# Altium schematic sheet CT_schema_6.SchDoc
size 582 x 363 mm
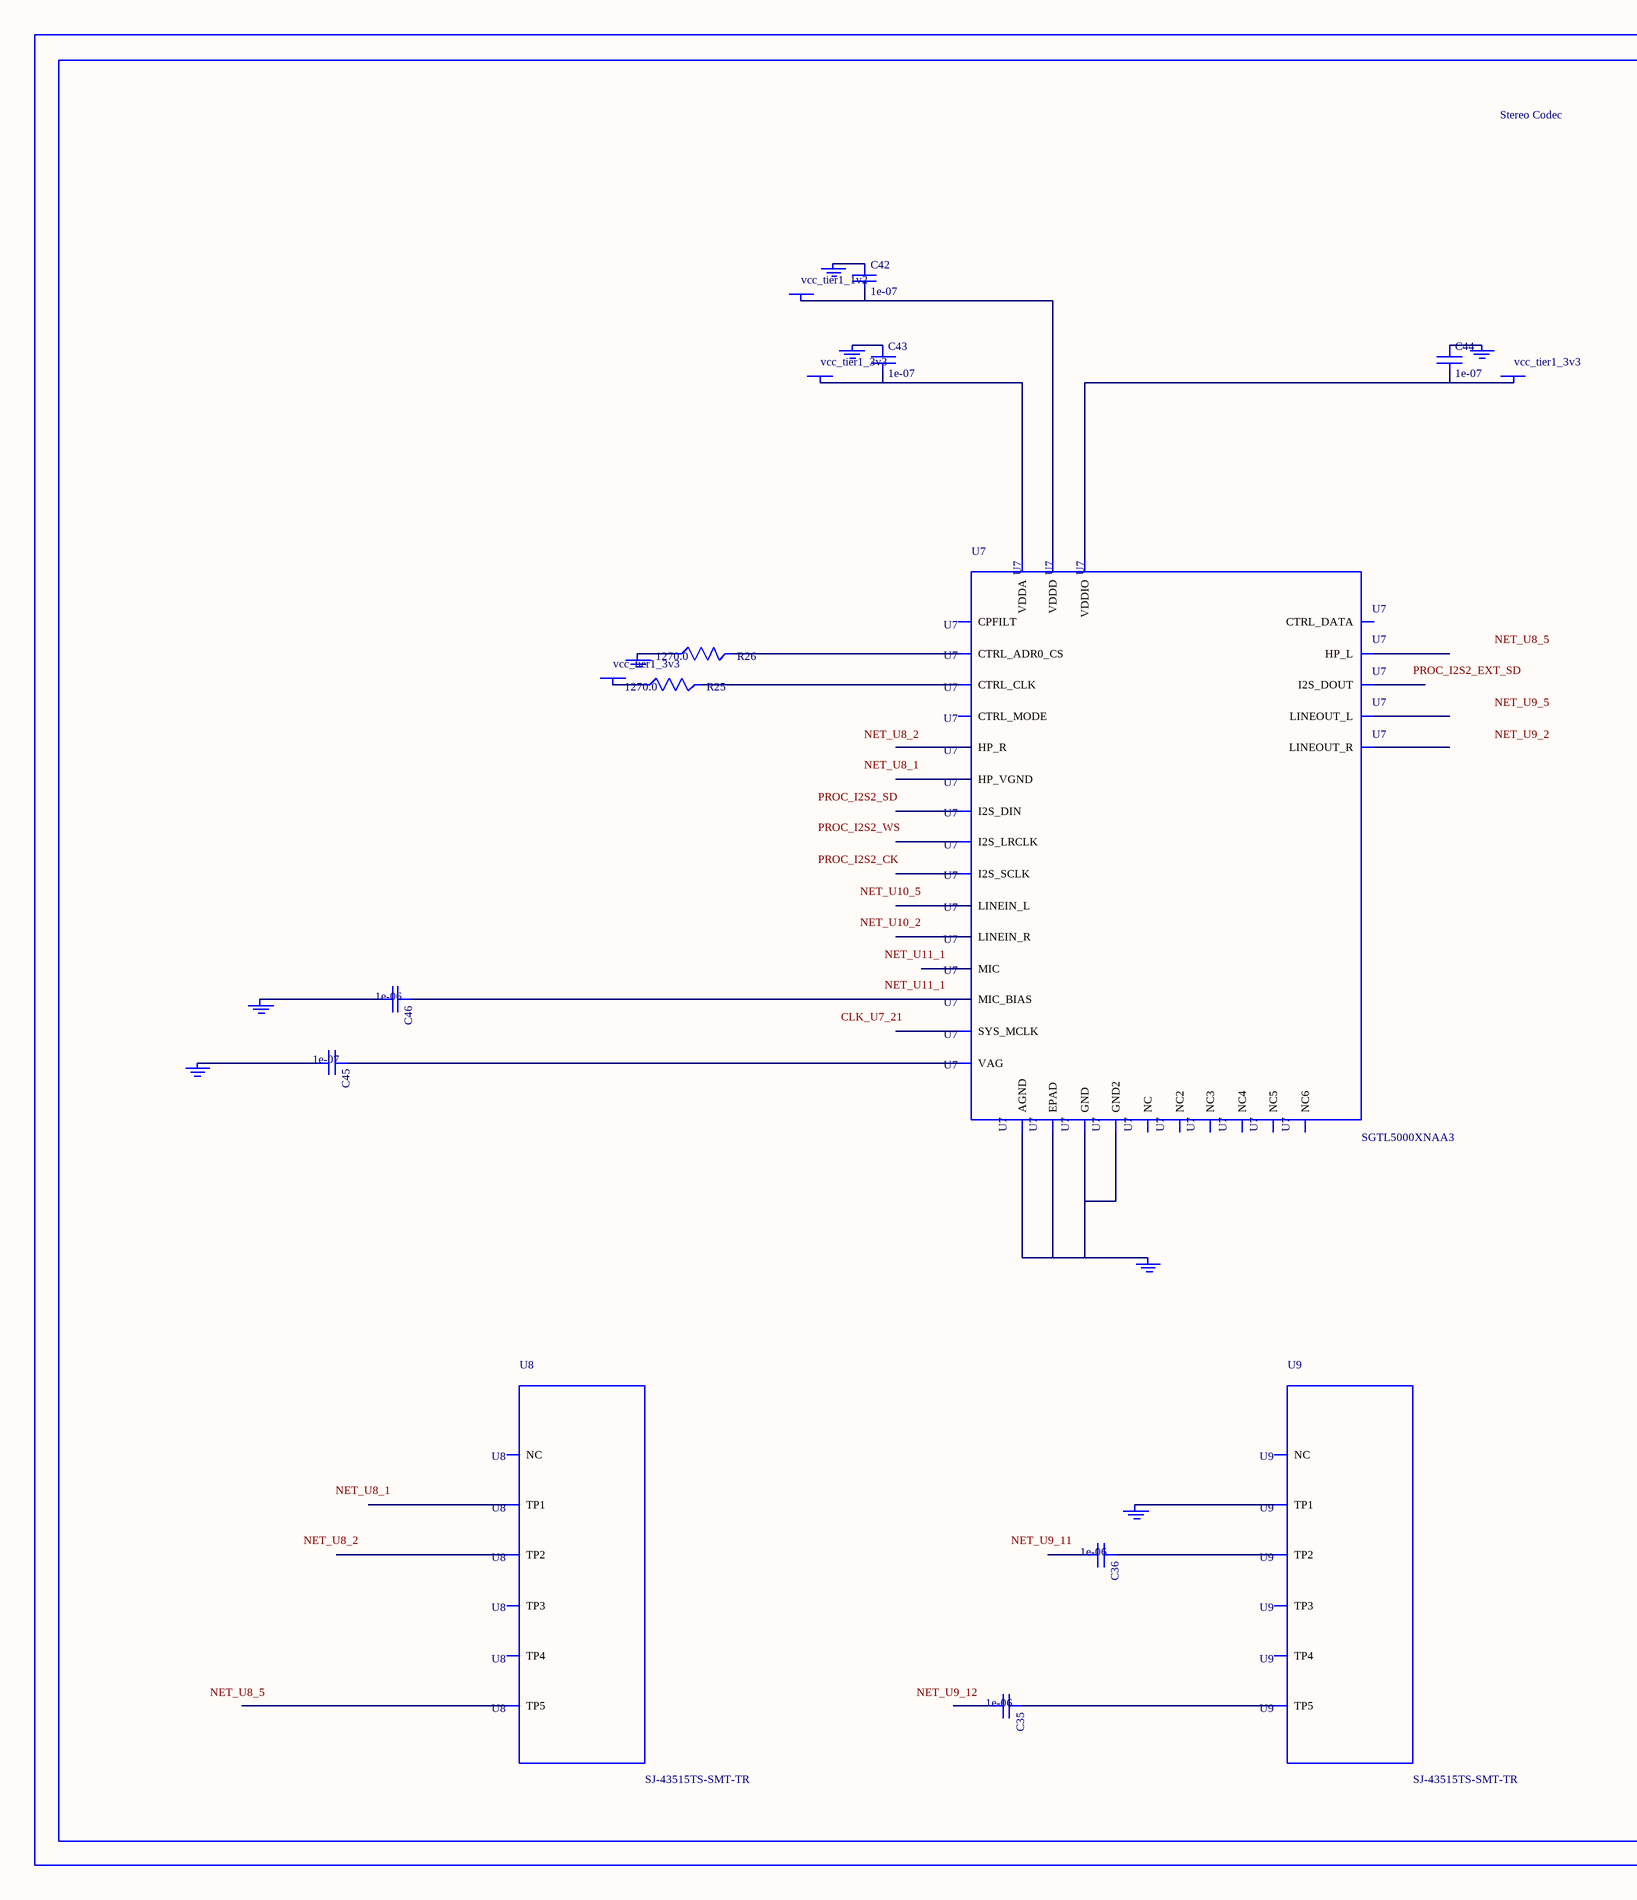
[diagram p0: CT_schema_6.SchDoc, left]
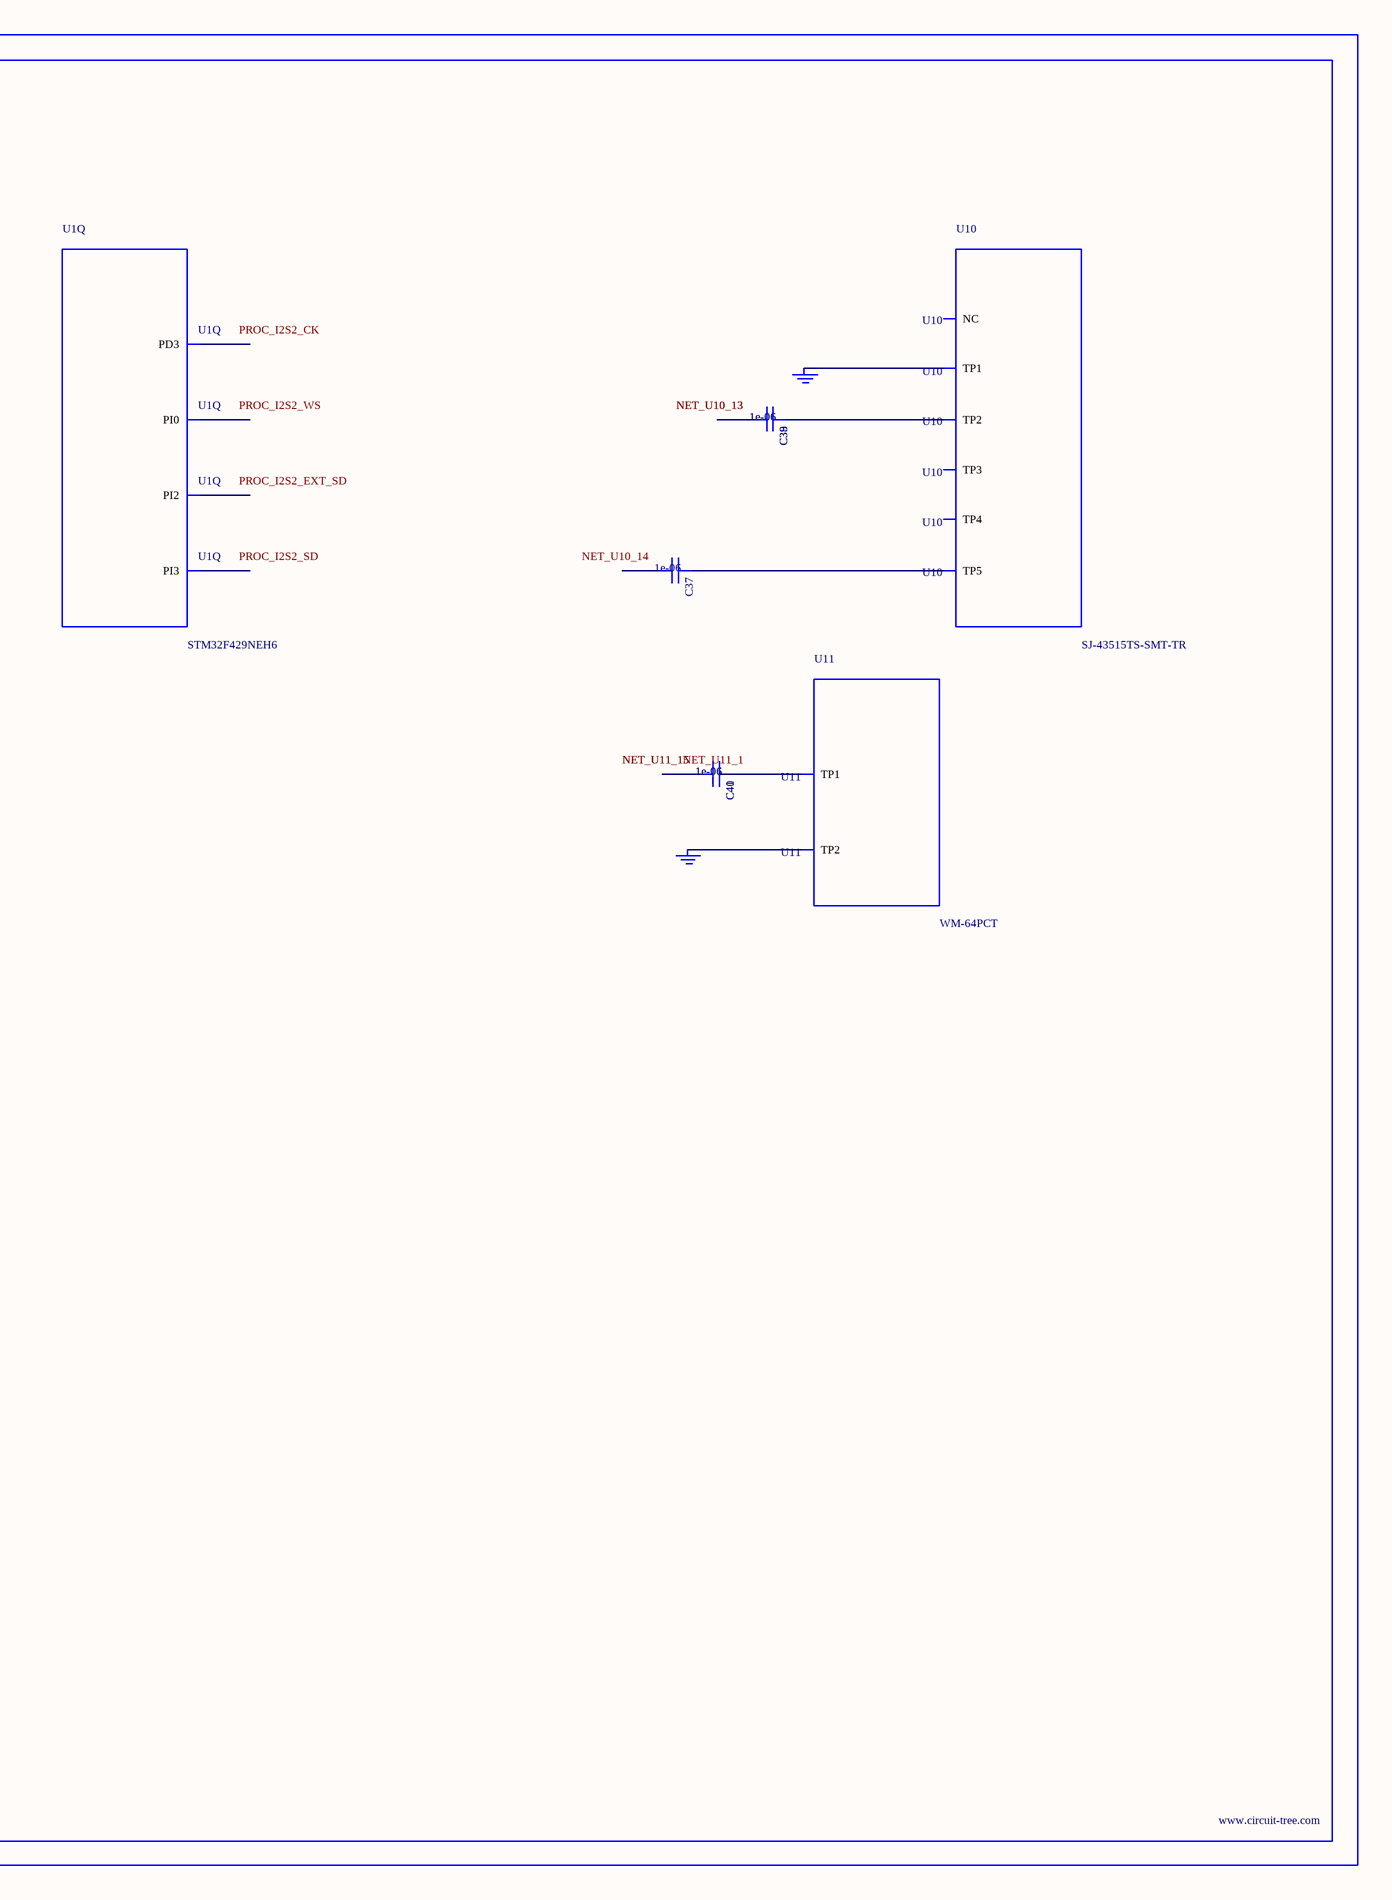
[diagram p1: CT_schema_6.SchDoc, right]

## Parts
BORDER5  (no value)
C35  1e-06  [C0603]
C36  1e-06  [C0603]
C37  1e-06  [C0603]
C38  1e-06  [C0603]
C39  1e-06  [C0603]
C40  1e-06  [C0603]
C41  1e-06  [C0603]
C42  1e-07  [C0402]
C43  1e-07  [C0402]
C44  1e-07  [C0402]
C45  1e-07  [C0402]
C46  1e-06  [C0603]
GND_INSTANCE_5_0  (no value)
GND_INSTANCE_5_1  (no value)
GND_INSTANCE_5_2  (no value)
GND_INSTANCE_5_3  (no value)
GND_INSTANCE_5_4  (no value)
GND_INSTANCE_5_5  (no value)
GND_INSTANCE_5_6  (no value)
GND_INSTANCE_5_7  (no value)
GND_INSTANCE_5_8  (no value)
GND_INSTANCE_5_9  (no value)
GND_INSTANCE_5_10  (no value)
POWER_INSTANCE_5_0  vcc_tier1_3v3
POWER_INSTANCE_5_1  vcc_tier1_3v3
POWER_INSTANCE_5_2  vcc_tier1_3v3
POWER_INSTANCE_5_3  vcc_tier1_1v2
R25  1270.0  [R0603]
R26  1270.0  [R0603]
U1  STM32F429NEH6  [TFBGA216]  (part Q of 17)
U7  SGTL5000XNAA3  [QFN-32]
U8  SJ-43515TS-SMT-TR  [SJ-43515TS-SMT-TR]
U9  SJ-43515TS-SMT-TR  [SJ-43515TS-SMT-TR]
U10  SJ-43515TS-SMT-TR  [SJ-43515TS-SMT-TR]
U11  WM-64PCT  [WM-64PC]

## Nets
NetC35_1: C35.1 U9.5(TP5)
NetC36_1: C36.1 U9.2(TP2)
NetC37_1: C37.1 U10.5(TP5)
NetC38_1: C38.1 C39.1 U10.2(TP2)
NetC38_2: C38.2 C39.2
NetC40_1: C40.1 C41.1 U11.1(TP1)
NetC40_2: C40.2 C41.2
NetC42_1: C42.1 GND_INSTANCE_5_5.0(GND)
NetC42_2: C42.2 POWER_INSTANCE_5_3.0(PWR) U7.30(VDDD)
NetC43_1: C43.1 GND_INSTANCE_5_1.0(GND)
NetC43_2: C43.2 POWER_INSTANCE_5_0.0(PWR) U7.5(VDDA)
NetC44_1: C44.1 GND_INSTANCE_5_4.0(GND)
NetC44_2: C44.2 POWER_INSTANCE_5_1.0(PWR) U7.20(VDDIO)
NetC45_1: C45.1 U7.10(VAG)
NetC45_2: C45.2 GND_INSTANCE_5_2.0(GND)
NetC46_1: C46.1 U7.16(MIC_BIAS)
NetC46_2: C46.2 GND_INSTANCE_5_3.0(GND)
NetGND_INSTANCE_5_0_0: GND_INSTANCE_5_0.0(GND) U7.1(GND) U7.3(GND2) U7.7(AGND) U7.EXP(EPAD)
NetGND_INSTANCE_5_6_0: GND_INSTANCE_5_6.0(GND) R26.1
NetGND_INSTANCE_5_7_0: GND_INSTANCE_5_7.0(GND) U9.1(TP1)
NetGND_INSTANCE_5_8_0: GND_INSTANCE_5_8.0(GND) GND_INSTANCE_5_9.0(GND) U10.1(TP1)
NetGND_INSTANCE_5_10_0: GND_INSTANCE_5_10.0(GND) U11.2(TP2)
NetPOWER_INSTANCE_5_2_0: POWER_INSTANCE_5_2.0(PWR) R25.1
NetR25_2: R25.2 U7.29(CTRL_CLK)
NetR26_2: R26.2 U7.31(CTRL_ADR0_CS)

Not connected (* = marked no-connect by the designer): C35 2; C36 2; C37 2; U1 C11(PD3) C13(PI3) C14(PI2) E14(PI0); U7 2(HP_R) 4(HP_VGND) 6(HP_L) 8(NC) 9(NC2) 11(LINEOUT_R) 12(LINEOUT_L) 13(LINEIN_R) 14(LINEIN_L) 15(MIC) 17(NC3) 18(CPFILT) 19(NC4) 21(SYS_MCLK) 22(NC5) 23(I2S_LRCLK) 24(I2S_SCLK) 25(I2S_DOUT) 26(I2S_DIN) 27(CTRL_DATA) 28(NC6) 32(CTRL_MODE); U8 1(TP1) 2(TP2) 3(TP3) 4(TP4) 5(TP5) 6(NC); U9 3(TP3) 4(TP4) 6(NC); U10 3(TP3) 4(TP4) 6(NC)

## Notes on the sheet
- Labels drawn without touching a wire or pin: CLK_U7_21, NET_U8_1, NET_U8_2, NET_U8_5, NET_U9_2, NET_U9_5, NET_U9_11, NET_U9_12, NET_U10_2, NET_U10_5, NET_U10_14, NET_U11_1, PROC_I2S2_CK, PROC_I2S2_EXT_SD, PROC_I2S2_SD, PROC_I2S2_WS

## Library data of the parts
BORDER5 = BORDER_PAGE5
C35-C41 C46 = C0603C105K3RACTU
C42-C45 = C0402C104K3RACTU
GND_INSTANCE_5_0-GND_INSTANCE_5_10 = GND
POWER_INSTANCE_5_0-POWER_INSTANCE_5_3 = PWR
R25 R26 = RC0603FR-071K27L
